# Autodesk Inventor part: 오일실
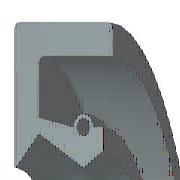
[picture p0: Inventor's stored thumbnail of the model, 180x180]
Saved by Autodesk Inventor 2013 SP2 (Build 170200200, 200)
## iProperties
IsCustomPart: 0
Company: 한국ATC센터
Created: 2014-10
Part Number: 오일실
Material: 고무
Description: 오일-실
Document SubType Name: Modeling
Standard: KS B 2804
Designer: KYOUNG IL JANG
Standards Organization: KS
Language: ko-KR
Size Designation: D - 17 32 8
Categories: <MemberInstance><Categories><Category DisplayName="샤프트 부품" InternalName="7f7aeb1f-a693-4053-b835-cee3144e0d98" Mnemonic="SHFT"><Category DisplayName="실링" Intern
Density: 0.93 g/cm^3
Mass: 2.28027 g
Surface Area: 32.1224 cm^2
Volume: 2.45191 cm^3
Author: KYOUNG IL JANG
Revision Number: 1
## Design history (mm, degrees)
revolve "본체" stored, may be unused: angle "d17" = 90 deg
revolve "스프링1" stored, may be unused: angle "d18" = 90 deg
body "Solid1"
sketch "스케치1"
  geometry: L1 (0, 16)-(8, 16); L2 (8, 14.25)-(1.75, 14.25); L3 (1.75, 10.25)-(4.9, 8.5); L4 (4.9, 8.5)-(0, 8.5); L5 (0, 0)-(9.586, 0) reference; L6 (4.9, 8.5)-(6.3, 9.375); L7 (0, 18)-(0, -3) reference; L8 (-1.941, 0)-(11.507, 0) reference; L9 (4.2, 10.6)-(1.75, 11.21); L10 (1.75, 11.21)-(1.75, 14.25); L11 (0, 16)-(0, 8.588); L12 (4.9, 8.5)-(0, 8.5); L13 (1.75, 10.25)-(0.152, 8.528); L14 (8, 16)-(8, 14.25); L15 (5.6, 10.6)-(6.3, 10.6); L16 (6.3, 10.6)-(6.3, 9.375); C1 r 0.455 at (4.9, 10.6); A1 r 0.7 centre (4.9, 10.6) between (5.6, 10.6) and (4.2, 10.6); A2 r 0.088 centre (0.088, 8.588) between (0, 8.588) and (0.152, 8.528); 1 further point
  constraints: 28 end point, 5 horizontal alignment, 5 point on line, 4 point on circle, 4 vertical alignment, 3 centre point, 3 tangent, 2 collinear, 2 horizontal, 2 perpendicular, 1 coincident, 1 parallel
  dimensions: "d0" = 32 diameter of L1 L5 (= SD2); "d1" = 1.75 distance of L1.end L2.start (= SD); "d2" = 0.91 diameter of C1 (= SPDI); "d3" = 1.4 diameter of A1 (= SPDA); "d4" = 17 diameter of L3.end L5 (= NND); "d5" = 20.5 diameter of L3.start L5 (= TKDM); "d7" = 22.42 diameter of L9.end L5 (= TKDM + 0.24 x SWDT); "d8" = 1.75 distance between parallel lines of L11 L10 (= SD); "d9" = 4.9 distance from line of L11 C1.centre (= SPDST); "d10" = 21.2 diameter of C1.centre L5 (= HLDM); "d11" = 0.0875 radius of A2 (= 0.25 x LAB); "d12" = 6.3 distance between parallel lines of L11 L16 (= SDI); "d13" = 18.75 diameter of L6.end L5 (= ABDM); "d14" = 8 distance from line of L11 L1.end (= SWDT)
fillet "모깎기1" dims "d6" = 0.3 (= RR)
other parameters: "SD2" = 32 [user parameter; used in 1 equation term], "SWDT" = 8 [user parameter; used in 2 equation terms], "RR" = 0.3 [user parameter; used in 1 equation term], "SD" = 1.75 [user parameter; used in 2 equation terms], "NND" = 17 [user parameter; used in 1 equation term], "SPDA" = 1.4 [user parameter; used in 1 equation term], "SPDI" = 0.91 [user parameter; used in 1 equation term], "TKDM" = 20.5 [user parameter; used in 2 equation terms], "HLDM" = 21.2 [user parameter; used in 1 equation term], "ABDM" = 18.75 [user parameter; used in 1 equation term], "SDI" = 6.3 [user parameter; used in 1 equation term], "SPDST" = 4.9 [user parameter; used in 1 equation term], "LAB" = 0.35 [user parameter; used in 1 equation term], "d15" = 0, "d16" = 0, "d19" = 0
